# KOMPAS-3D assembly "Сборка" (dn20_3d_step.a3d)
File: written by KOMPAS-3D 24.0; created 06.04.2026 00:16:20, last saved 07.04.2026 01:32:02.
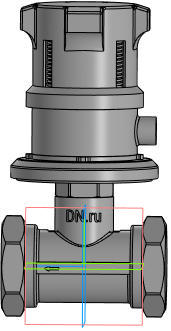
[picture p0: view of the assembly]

Document properties: Автор: tyuri; Полное имя файла: D:\Аутсорс\VBA0000E-T Клапан балансировочный автоматический DN.ru\DN25\Исходные файлы\dn20_3d_step.a3d

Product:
- Component [detail]: Деталь  | qty 1  | Автор: tyuri; additional columns: Типовые; source file: Деталь - Деталь.m3d
- Component [detail]: Деталь  | designation Деталь_1  | qty 1  | Автор: tyuri; additional columns: Типовые; source file: Деталь_1 - Деталь.m3d
- Component [detail]: Деталь  | qty 1  | Автор: tyuri; additional columns: Типовые; source file: Деталь_3 - Деталь.m3d
- Part/product: Сборка
    Масса: 1.195907

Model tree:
1. Эскиз:3  (labels: Грань.Твердое тело1)
2. Элемент выдавливания:2
     Расстояние 2 = 10
3. Элемент вращения:1  (labels: Грань.Твердое тело1)
     Угол 1 = 360
4. Смещенная плоскость:1
     Расстояние = -13
5. Эскиз:4
6. Смещенная плоскость:2
     Расстояние = 13
7. Эскиз:5
8. Элемент выдавливания:6  (labels: Грань.Твердое тело1)
     Расстояние 2 = 0.509174
9. Элемент выдавливания:7  (with: Грань.Элемент выдавливания:6)
     Расстояние 1 = -0.545716
10. Эскиз:9  (with: Грань.Элемент выдавливания:6)
11. Элемент вращения:3  (with: Грань.Элемент выдавливания:6)
     Угол 1 = 360
12. Эскиз:10  (with: Грань.Элемент выдавливания:6)
13. Элемент выдавливания:8  (with: Грань.Элемент вращения:1, Грань.Элемент выдавливания:1)  (labels: Грань.Твердое тело1; Твердое тело1)
     Расстояние 1 = 0.001

Referenced files in D:\Аутсорс\VBA0000E-T Клапан балансировочный автоматический DN.ru\DN25\Исходные файлы\: Деталь - Деталь.m3d, Деталь_1 - Деталь.m3d, Деталь_3 - Деталь.m3d
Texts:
  Точка начала. Х
  Точка начала. Y
  Точка начала. Z
  ЛС59
  DN25      PN16
  Деталь_1 Деталь
  Ось Z.Начало координат
  Ось Y.Начало координат
  Плоскость ZY.Начало координат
